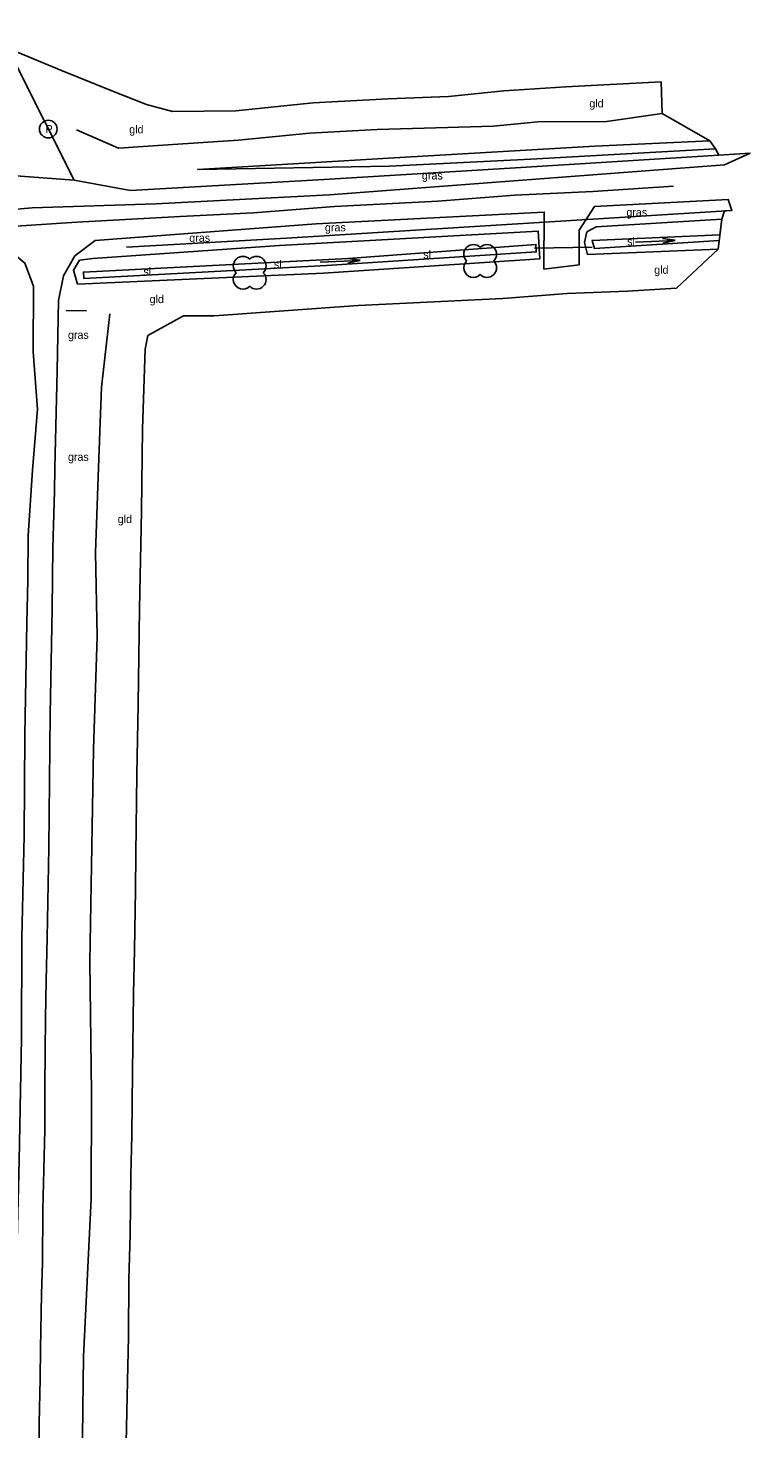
# Model space of a CAD drawing. Extents: x 154825 to 158680, y 370717 to 378075.
# Drawn here: x 156606.6 to 156696.9, y 375862.1 to 376037.2 of the extents above; entities that cross this region are included whole.
import ezdxf

# ---------------------------------------------------------------- set-up
doc = ezdxf.new("R2010")
doc.units = 0
for name, color, linetype in [('boom', 7, 'Continuous'), ('cultuurscheiding', 7, 'Continuous'), ('duiker lijn', 7, 'Continuous'), ('grasland_productiegrasl(vs)', 7, 'Continuous'), ('grazige vegetatie(vs)', 7, 'Continuous'), ('hoogteverschillijn', 7, 'Continuous'), ('insteek sloot', 7, 'Continuous'), ('maaiveldlijn algemeen - bomenrij', 7, 'Continuous'), ('maaiveldlijn algemeen - onverhard', 7, 'Continuous'), ('paal', 7, 'Continuous'), ('Sloot bodem', 7, 'Continuous'), ('sloot(vs)', 7, 'Continuous'), ('stroomrichting  watergangen', 7, 'Continuous'), ('vlak_Bos', 7, 'Continuous'), ('vlak_Grasland', 7, 'Continuous'), ('vlak_Grazige_vegetatie', 7, 'Continuous')]:
    doc.layers.add(name, color=color, linetype=linetype)

msp = doc.modelspace()

# ---------------------------------------------------------------- linework, layer by layer
at = {"layer": 'boom'}
for centre, start, end in [((156662.33, 376008.91), 45, 225), ((156664.03, 376008.91), 315, 135), ((156633.5, 376007.44), 45, 225), ((156635.2, 376007.44), 315, 135), ((156662.33, 376007.21), 134.7431, 315), ((156664.03, 376007.21), 225, 45), ((156633.5, 376005.75), 134.7431, 315), ((156635.2, 376005.75), 225, 45)]:
    msp.add_arc(centre, 1.2, start, end, dxfattribs=at)
at = {"layer": 'cultuurscheiding'}
msp.add_lwpolyline([(156604.54, 376018.73), (156612.4, 376018.17)], dxfattribs=at)
at = {"layer": 'duiker lijn'}
msp.add_lwpolyline([(156677.19, 376009.81), (156669.96, 376009.68)], dxfattribs=at)
at = {"layer": 'hoogteverschillijn'}
for points in [[(156604.88, 376034.31), (156610.79, 376031.88), (156617.32, 376029.23), (156621.46, 376027.63), (156624.69, 376026.73), (156632.63, 376026.83), (156642.28, 376027.82), (156651.67, 376028.35), (156659.22, 376028.61), (156666.15, 376029.34), (156673.91, 376029.82), (156685.81, 376030.47), (156685.94, 376026.48), (156678.99, 376025.48), (156670.4, 376025.46), (156664.83, 376024.91), (156657.65, 376024.69), (156650.29, 376024.51), (156641.83, 376024.02), (156632.93, 376023.17), (156624.09, 376022.6), (156617.93, 376022.16), (156612.67, 376024.46)], [(156691.91, 376023.08), (156677.53, 376022.43), (156653.12, 376020.98), (156627.85, 376019.51), (156651.83, 376019.93), (156669.5, 376020.77), (156692.61, 376022.08), (156691.91, 376023.08)], [(156603.2, 376012.28), (156612.73, 376012.91), (156625.64, 376013.64), (156634.82, 376014.09), (156644.97, 376014.87), (156657.87, 376015.55), (156667.51, 376016.28), (156677.26, 376016.76), (156687.34, 376017.42)], [(156687.73, 376004.67), (156681.61, 376004.31), (156674.04, 376004.02), (156666.02, 376003.36), (156656.55, 376002.9), (156647.93, 376002.49), (156629.89, 376001.21), (156626.08, 376001.2), (156621.6, 375998.75), (156621.27, 375997.05), (156620.95, 375987.08), (156620.83, 375976.8), (156620.58, 375964.61), (156620.41, 375952.69), (156620.24, 375943.9), (156620.09, 375933.97), (156620.07, 375929.45), (156619.92, 375921.93), (156619.82, 375916.52), (156619.69, 375906.67), (156619.61, 375898.8), (156619.46, 375893.79), (156619.41, 375886.34), (156619.25, 375880.83), (156619.18, 375873.59), (156619.05, 375868.05), (156618.91, 375860.36)], [(156613.95, 376001.83), (156611.41, 376001.86)], [(156609.42, 375662.66), (156609.78, 375674.29), (156610.1, 375684.96), (156610.88, 375698.58), (156611.14, 375712.85), (156611.06, 375733.23), (156610.98, 375746.48), (156611.57, 375760.11), (156611.49, 375774.3), (156611.79, 375788.36), (156612.38, 375801.56), (156612.38, 375820.58), (156612.86, 375832.96), (156613.32, 375851.18), (156613.56, 375871.13), (156614.52, 375890.86), (156614.58, 375904.1), (156614.35, 375920.44), (156614.81, 375947.02), (156615.25, 375961.15), (156615.07, 375971.65), (156615.43, 375982.27), (156615.82, 375992.29), (156616.86, 376001.44)]]:
    msp.add_lwpolyline(points, dxfattribs=at)
at = {"layer": 'insteek sloot'}
for points in [[(156693.42, 376013.31), (156692.95, 376009.55), (156676.62, 376008.88), (156676.23, 376010.37), (156676.53, 376011.7), (156677.68, 376012.34), (156693.42, 376013.31)], [(156612.82, 376005.18), (156612.3, 376006.92), (156613.06, 376008.15), (156614.72, 376008.37), (156638.09, 376010.02), (156670.44, 376011.79), (156670.65, 376008.35), (156643.59, 376006.53), (156612.82, 376005.18)]]:
    msp.add_lwpolyline(points, dxfattribs=at)
at = {"layer": 'maaiveldlijn algemeen - bomenrij'}
for points in [[(156693.04, 376021.31), (156667.6, 376019.69), (156643.66, 376018.26), (156619.44, 376016.89), (156612.4, 376018.17), (156604.85, 376033.15), (156604.03, 376034.4)], [(156694.66, 376014.39), (156670.57, 376012.89), (156638.96, 376010.93), (156618.94, 376009.8)]]:
    msp.add_lwpolyline(points, dxfattribs=at)
at = {"layer": 'maaiveldlijn algemeen - onverhard'}
for points in [[(156433.39, 376003.01), (156460.31, 376004.82), (156484.66, 376006.15), (156513.94, 376008.36), (156539.1, 376009.68), (156563.01, 376011.28), (156586.14, 376012.86), (156607.15, 376014.69), (156622.62, 376015.22), (156644.34, 376016.34), (156693.74, 376020.07)], [(156609.97, 375982.21), (156610.28, 375994.35), (156610.45, 376003.13), (156611.06, 376006.2), (156612.46, 376008.69), (156615.01, 376010.61), (156642.67, 376012.71), (156671.19, 376014.18), (156671.15, 376007.06), (156675.55, 376007.57), (156675.54, 376011.9), (156677.46, 376014.86), (156694.19, 376015.75)], [(156432.8, 375999.17), (156458.8, 376000.56), (156490.83, 376003.18), (156514.06, 376004.16), (156539.42, 376006.4), (156562.97, 376007.51), (156586.55, 376009.57), (156598.96, 376010.13), (156604.22, 376009.52), (156606.24, 376007.8), (156607.29, 376004.92), (156607.27, 375996.72), (156607.79, 375989.55), (156607.16, 375981.92)], [(156604.91, 375859.72), (156604.93, 375872.44), (156605.52, 375895.64), (156605.8, 375910.92), (156605.85, 375923.43), (156606.12, 375936.28), (156606.21, 375948.78), (156606.49, 375962.82), (156606.61, 375968.16), (156606.64, 375973.76), (156607.16, 375981.92)], [(156609.97, 375982.21), (156609.92, 375979.27), (156609.74, 375972.23), (156609.64, 375964.57), (156609.37, 375951.37), (156609.21, 375934.72), (156609, 375923.47), (156608.9, 375918.11), (156608.79, 375913.46), (156608.74, 375904.89), (156608.71, 375899.49), (156608.6, 375894.49), (156608.48, 375889.47), (156608.41, 375882.8), (156608.29, 375878.93), (156608.2, 375872.16), (156608.15, 375868.34), (156608.01, 375862.8), (156607.93, 375855.08)]]:
    msp.add_lwpolyline(points, dxfattribs=at)
at = {"layer": 'paal'}
msp.add_circle((156609.15, 376024.55), 1.1, dxfattribs=at)
at = {"layer": 'Sloot bodem'}
for points in [[(156693.09, 376010.64), (156677.48, 376009.61), (156677.18, 376010.64), (156693.17, 376011.33)], [(156643.94, 376007.52), (156613.59, 376005.88), (156613.54, 376006.67), (156646.68, 376008.37), (156670.15, 376010.14), (156670.2, 376009.2), (156643.94, 376007.52)]]:
    msp.add_lwpolyline(points, dxfattribs=at)
at = {"layer": 'stroomrichting  watergangen'}
for p, q in [((156682.59, 376010.41), (156687.58, 376010.64)), ((156687.56, 376010.66), (156685.99, 376010.86)), ((156687.58, 376010.64), (156686.04, 376010.3)), ((156643.18, 376007.92), (156648.16, 376008.14)), ((156648.15, 376008.16), (156646.58, 376008.36)), ((156648.16, 376008.14), (156646.62, 376007.8))]:
    msp.add_line(p, q, dxfattribs=at)
at = {"layer": 'vlak_Bos'}
for points in [[(156537.32, 376180.85), (156543.83, 376166.91), (156550.14, 376152.66), (156562.27, 376126.6), (156568.66, 376112.12), (156576.24, 376095.35), (156581.55, 376083.58), (156586.98, 376071.77), (156593.52, 376057.34), (156598.81, 376046.03), (156604.03, 376034.4), (156604.85, 376033.15), (156612.4, 376018.17), (156604.54, 376018.73), (156600.26, 376028.75), (156593.98, 376037.13), (156575.26, 376075.98), (156562.03, 376105.32), (156549.71, 376132.58), (156537.65, 376159.52), (156527.1, 376182.74)], [(156606.24, 376007.8), (156607.29, 376004.92), (156607.27, 375996.72), (156607.79, 375989.55), (156607.16, 375981.92), (156606.64, 375973.76), (156606.61, 375968.16)]]:
    msp.add_lwpolyline(points, dxfattribs=at)
at = {"layer": 'vlak_Grasland'}
msp.add_lwpolyline([(156621.46, 376027.63), (156624.69, 376026.73), (156632.63, 376026.83), (156642.28, 376027.82), (156651.67, 376028.35), (156659.22, 376028.61), (156666.15, 376029.34), (156673.91, 376029.82), (156685.81, 376030.47), (156685.94, 376026.48), (156691.91, 376023.08), (156692.61, 376022.08), (156693.04, 376021.31), (156667.6, 376019.69), (156643.66, 376018.26), (156619.44, 376016.89), (156612.4, 376018.17), (156604.85, 376033.15), (156604.03, 376034.4), (156604.88, 376034.31), (156610.79, 376031.88), (156617.32, 376029.23)], close=True, dxfattribs=at)
at = {"layer": 'vlak_Grazige_vegetatie'}
for points in [[(156604.54, 376018.73), (156612.4, 376018.17), (156619.44, 376016.89), (156643.66, 376018.26), (156667.6, 376019.69), (156693.04, 376021.31), (156696.93, 376021.56), (156693.74, 376020.07), (156644.34, 376016.34), (156622.62, 376015.22), (156607.15, 376014.69), (156586.14, 376012.86)], [(156607.93, 375855.08), (156608.01, 375862.8), (156608.15, 375868.34), (156608.2, 375872.16), (156608.29, 375878.93), (156608.41, 375882.8), (156608.48, 375889.47), (156608.6, 375894.49), (156608.71, 375899.49), (156608.74, 375904.89), (156608.79, 375913.46), (156608.9, 375918.11), (156609, 375923.47), (156609.21, 375934.72), (156609.37, 375951.37), (156609.64, 375964.57), (156609.74, 375972.23), (156609.92, 375979.27), (156609.97, 375982.21), (156610.28, 375994.35), (156610.45, 376003.13), (156611.06, 376006.2), (156612.46, 376008.69), (156615.01, 376010.61), (156642.67, 376012.71), (156671.19, 376014.18), (156671.15, 376007.06), (156675.55, 376007.57), (156675.54, 376011.9), (156677.46, 376014.86), (156694.19, 376015.75), (156694.66, 376014.39), (156693.75, 376014.34), (156693.42, 376013.31), (156677.68, 376012.34), (156676.53, 376011.7), (156676.23, 376010.37), (156676.62, 376008.88), (156692.95, 376009.55), (156687.73, 376004.67), (156681.61, 376004.31), (156674.04, 376004.02), (156666.02, 376003.36), (156656.55, 376002.9), (156647.93, 376002.49), (156629.89, 376001.21), (156626.08, 376001.2), (156621.6, 375998.75), (156621.27, 375997.05), (156620.95, 375987.08), (156620.83, 375976.8), (156620.58, 375964.61), (156620.41, 375952.69), (156620.24, 375943.9), (156620.09, 375933.97), (156620.07, 375929.45), (156619.92, 375921.93), (156619.82, 375916.52), (156619.69, 375906.67), (156619.61, 375898.8), (156619.46, 375893.79), (156619.41, 375886.34), (156619.25, 375880.83), (156619.18, 375873.59), (156619.05, 375868.05), (156618.91, 375860.36)]]:
    msp.add_lwpolyline(points, dxfattribs=at)
for points in [[(156677.18, 376010.64), (156677.48, 376009.61), (156693.09, 376010.64), (156692.95, 376009.55), (156676.62, 376008.88), (156676.23, 376010.37), (156676.53, 376011.7), (156677.68, 376012.34), (156693.42, 376013.31), (156693.17, 376011.33)], [(156670.65, 376008.35), (156670.44, 376011.79), (156638.09, 376010.02), (156614.72, 376008.37), (156613.06, 376008.15), (156612.3, 376006.92), (156612.82, 376005.18), (156643.59, 376006.53)], [(156670.44, 376011.79), (156670.65, 376008.35), (156643.59, 376006.53), (156612.82, 376005.18), (156612.3, 376006.92), (156613.06, 376008.15), (156614.72, 376008.37), (156638.09, 376010.02)], [(156613.54, 376006.67), (156613.59, 376005.88), (156643.94, 376007.52), (156670.2, 376009.2), (156670.15, 376010.14), (156646.68, 376008.37)]]:
    msp.add_lwpolyline(points, close=True, dxfattribs=at)

# ---------------------------------------------------------------- texts
at = {"layer": 'grasland_productiegrasl(vs)'}
for p in [(156676.83, 376027.26), (156619.28, 376024.02), (156684.95, 376006.46), (156621.83, 376002.8), (156617.84, 375975.31)]:
    msp.add_text('gld', height=1, dxfattribs=at).set_placement(p)
at = {"layer": 'grazige vegetatie(vs)'}
for p in [(156655.89, 376018.25), (156681.47, 376013.66), (156643.76, 376011.77), (156626.79, 376010.46), (156611.62, 375998.33), (156611.62, 375983.08)]:
    msp.add_text('gras', height=1, dxfattribs=at).set_placement(p)
at = {"layer": 'paal'}
msp.add_text('P', height=1, dxfattribs=at).set_placement((156608.82, 376024.05))
at = {"layer": 'sloot(vs)'}
for p in [(156681.56, 376010.01), (156656.06, 376008.37), (156621.05, 376006.24), (156637.37, 376007.14)]:
    msp.add_text('sl', height=1, dxfattribs=at).set_placement(p)

doc.saveas('drawing.dxf')
